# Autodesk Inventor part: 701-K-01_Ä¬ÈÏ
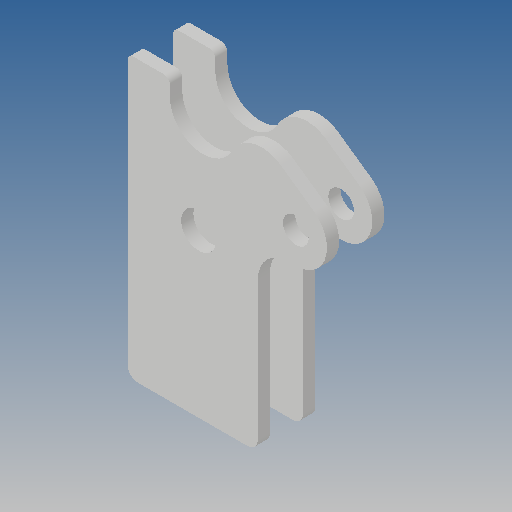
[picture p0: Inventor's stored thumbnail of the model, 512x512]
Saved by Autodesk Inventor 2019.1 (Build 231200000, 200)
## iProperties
Created: 2010-06
Part Number: 701-K-01_Ä¬ÈÏ
Material: Ogólny
Document SubType Name: Modeling
Designer: CADENGINEERING4
Density: 1 g/cm^3
Appearance: Domyślna
Author: CADENGINEERING4
Revision Number: ÈÎºÎ
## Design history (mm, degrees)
feature "NONE"
feature "NONE:1"
node "Bryła1"
node "Bryła2"
